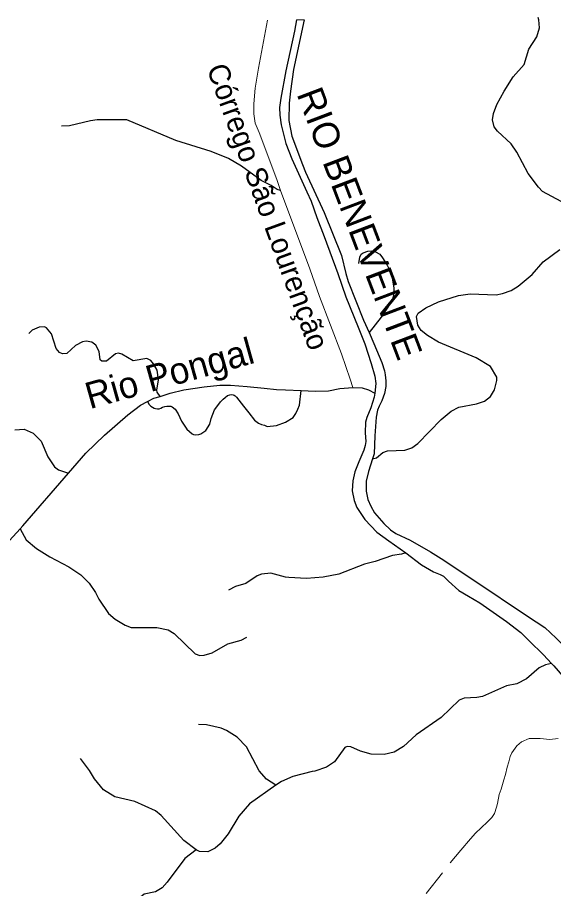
# Model space of a CAD drawing. Extents: x 317.8 to 344.1, y 7676.8 to 7704.8.
# Drawn here: x 325.558 to 327.586, y 7701.313 to 7704.608 of the extents above; entities that cross this region are included whole.
import ezdxf
from ezdxf.enums import TextEntityAlignment as Align

# ---------------------------------------------------------------- set-up
doc = ezdxf.new("R2010")
doc.units = 0
doc.header["$LTSCALE"] = 0.032
doc.linetypes.add('SHORT_DASHED', pattern=[2.7, 1.5, -1.2])
for name, color, linetype, lineweight in [('1', 7, 'Continuous', 13), ('2', 7, 'Continuous', 25), ('21', 7, 'SHORT_DASHED', 13), ('62', 7, 'SHORT_DASHED', 13), ('7', 7, 'Continuous', 25)]:
    doc.layers.add(name, color=color, linetype=linetype, lineweight=lineweight)
doc.layers.add('61', color=7, linetype='Continuous')

msp = doc.modelspace()

# ---------------------------------------------------------------- linework, layer by layer
at = {"layer": '1'}
for points in [[(326.5047, 7704.597), (326.4697, 7704.4161), (326.4572, 7704.3394), (326.453, 7704.2802), (326.453, 7704.2427), (326.458, 7704.2076), (326.4722, 7704.1718), (326.5389, 7703.995), (326.5534, 7703.953)], [(326.5534, 7703.953), (326.6648, 7703.6563), (326.7007, 7703.5521), (326.7841, 7703.3352), (326.8166, 7703.2393), (326.8268, 7703.2079)]]:
    msp.add_lwpolyline(points, dxfattribs=at)
at = {"layer": '2'}
for points in [[(326.6144, 7704.5981), (326.6062, 7704.5552), (326.5733, 7704.4056), (326.5545, 7704.3026), (326.5499, 7704.2663), (326.551, 7704.2382), (326.5557, 7704.2008), (326.5733, 7704.1306), (326.5967, 7704.0732), (326.6529, 7703.948), (326.6693, 7703.9129), (326.6903, 7703.8508), (326.7184, 7703.7794), (326.7699, 7703.639), (326.8003, 7703.5512), (326.8472, 7703.4365), (326.8729, 7703.3733), (326.8963, 7703.2995), (326.9104, 7703.2515), (326.9139, 7703.2234), (326.9097, 7703.1865)], [(326.6424, 7704.5984), (326.6025, 7704.4105), (326.5911, 7704.3285), (326.5865, 7704.2829), (326.5854, 7704.218), (326.5968, 7704.1588), (326.6367, 7704.0518), (326.648, 7704.0222), (326.7186, 7703.8696), (326.7836, 7703.7067), (326.8006, 7703.6395), (326.8097, 7703.6088), (326.8678, 7703.463), (326.8885, 7703.4156)], [(326.8885, 7703.4156), (326.9065, 7703.3742), (326.9361, 7703.3025), (326.9464, 7703.2706), (326.9498, 7703.2558), (326.9521, 7703.233), (326.9521, 7703.2114), (326.9464, 7703.1852), (326.9361, 7703.1578), (326.927, 7703.1373), (326.9202, 7703.1225), (326.9157, 7703.0963), (326.91, 7703.0257), (326.9077, 7702.9574), (326.9014, 7702.938)], [(326.9097, 7703.1865), (326.908, 7703.1719), (326.8952, 7703.131), (326.8799, 7703.0947), (326.8753, 7703.0771), (326.8741, 7703.0362), (326.8764, 7703.0034), (326.8741, 7702.9894), (326.8682, 7702.9706), (326.8495, 7702.9273), (326.8343, 7702.8887), (326.8273, 7702.8548), (326.8249, 7702.8173), (326.8319, 7702.781), (326.8425, 7702.7541), (326.8729, 7702.7096), (326.9174, 7702.6616), (326.963, 7702.6289), (327.0274, 7702.5832)], [(326.9014, 7702.938), (326.886, 7702.8902), (326.8769, 7702.8538), (326.8769, 7702.8162), (326.8838, 7702.7843), (326.8952, 7702.7593), (326.9088, 7702.7342), (326.9441, 7702.6943), (326.9692, 7702.6704), (326.9897, 7702.6556), (327.0443, 7702.6306), (327.1206, 7702.5862), (327.1605, 7702.5611), (327.2846, 7702.4791), (327.4873, 7702.3436), (327.5534, 7702.3003), (327.5955, 7702.2605), (327.6308, 7702.2252)], [(327.0274, 7702.5832), (327.0871, 7702.5376), (327.1316, 7702.5106), (327.1573, 7702.5013), (327.1702, 7702.4942), (327.1889, 7702.4755), (327.2276, 7702.4404), (327.2638, 7702.4193), (327.3072, 7702.3936), (327.4078, 7702.3234), (327.4617, 7702.2812), (327.4944, 7702.2496), (327.5483, 7702.1969), (327.5785, 7702.1649)], [(327.5785, 7702.1649), (327.5869, 7702.156), (327.6279, 7702.1092)]]:
    msp.add_lwpolyline(points, dxfattribs=at)
at = {"layer": '21'}
msp.add_lwpolyline([(327.1038, 7701.2943), (327.1947, 7701.4103), (327.2352, 7701.4592), (327.2715, 7701.5011), (327.2911, 7701.5235), (327.312, 7701.543), (327.3358, 7701.5654), (327.3525, 7701.5821), (327.3623, 7701.5975), (327.3707, 7701.6213), (327.3735, 7701.6352), (327.3805, 7701.6688), (327.3875, 7701.6897), (327.3986, 7701.7247), (327.4042, 7701.7442), (327.4112, 7701.7722), (327.4168, 7701.7931), (327.4224, 7701.8127), (327.428, 7701.8267), (327.4475, 7701.8532), (327.4643, 7701.8686), (327.4937, 7701.8811), (327.5356, 7701.8811), (327.5719, 7701.877), (327.604, 7701.8811)], dxfattribs=at)
at = {"layer": '62'}
msp.add_line((326.6144, 7704.5981), (326.6424, 7704.5984), dxfattribs=at)
at = {"layer": '7'}
for points in [[(327.6142, 7703.9111), (327.5447, 7703.9491), (327.5287, 7703.9651), (327.4899, 7704.0174), (327.4468, 7704.0985), (327.4256, 7704.1299), (327.3737, 7704.1771), (327.3617, 7704.1938), (327.3557, 7704.2199), (327.3594, 7704.2438), (327.3721, 7704.2778), (327.3994, 7704.3292), (327.4331, 7704.3826), (327.4746, 7704.4292), (327.4931, 7704.4874), (327.5223, 7704.5345), (327.5325, 7704.5682), (327.53, 7704.5986), (327.5274, 7704.6075)], [(326.5534, 7703.953), (326.5404, 7703.9574), (326.5184, 7703.9724), (326.4804, 7703.9904), (326.4059, 7704.0446), (326.357, 7704.0735), (326.291, 7704.1007), (326.1577, 7704.1423), (325.9728, 7704.2198), (325.8603, 7704.2204), (325.8342, 7704.2171), (325.7552, 7704.1977), (325.7249, 7704.1961)], [(326.8492, 7703.6769), (326.8533, 7703.7007), (326.859, 7703.7121), (326.8656, 7703.7179), (326.8836, 7703.7236), (326.8975, 7703.7244), (326.9122, 7703.7211), (326.9286, 7703.7129), (326.9393, 7703.699), (326.9565, 7703.6712), (326.9704, 7703.6425), (326.9769, 7703.6155), (326.9819, 7703.5835), (326.981, 7703.559), (326.9769, 7703.5418), (326.9598, 7703.5123), (326.9335, 7703.4738), (326.8885, 7703.4156)], [(326.9014, 7702.938), (326.917, 7702.9424), (326.9408, 7702.962), (326.9582, 7702.9687), (327.0237, 7702.9709), (327.0495, 7702.9802), (327.0733, 7702.9961), (327.1614, 7703.0874), (327.1987, 7703.1185), (327.2284, 7703.1337), (327.294, 7703.1463), (327.3253, 7703.1564), (327.3472, 7703.1738), (327.3631, 7703.1991), (327.3711, 7703.234), (327.3711, 7703.2467), (327.3475, 7703.2872), (327.2937, 7703.3207), (327.1509, 7703.3798), (327.1095, 7703.4047), (327.0859, 7703.4234), (327.073, 7703.4443), (327.068, 7703.4771), (327.0741, 7703.4891), (327.103, 7703.5089), (327.1513, 7703.5322), (327.2259, 7703.5564), (327.2705, 7703.5628), (327.3692, 7703.5588), (327.3926, 7703.563), (327.426, 7703.5751), (327.4526, 7703.5919), (327.5045, 7703.6359), (327.5466, 7703.6835), (327.6102, 7703.7295)], [(326.0986, 7703.1746), (326.0874, 7703.1907), (326.0859, 7703.1985), (326.0923, 7703.2369), (326.0865, 7703.2737), (326.0734, 7703.298), (326.0634, 7703.3096), (326.0477, 7703.318), (325.9959, 7703.3086), (325.9529, 7703.3336), (325.9403, 7703.3379), (325.929, 7703.3359), (325.8949, 7703.308), (325.8771, 7703.3072), (325.8717, 7703.3126), (325.8681, 7703.3438), (325.8552, 7703.3688), (325.8397, 7703.3793), (325.8184, 7703.3827), (325.8042, 7703.381), (325.7786, 7703.3671), (325.7455, 7703.3364), (325.7284, 7703.3353), (325.7176, 7703.3403), (325.7047, 7703.3558), (325.6874, 7703.4108), (325.669, 7703.4336), (325.6603, 7703.4373), (325.6408, 7703.4364), (325.6142, 7703.425), (325.601, 7703.4129)], [(326.0502, 7703.1547), (326.0563, 7703.1441), (326.0626, 7703.1377), (326.069, 7703.134), (326.075, 7703.1306), (326.0806, 7703.1284), (326.088, 7703.1273), (326.0948, 7703.128), (326.1004, 7703.1306), (326.1075, 7703.1336), (326.1164, 7703.1359), (326.1239, 7703.137), (326.1329, 7703.1377), (326.1388, 7703.1374), (326.1441, 7703.1355), (326.1555, 7703.1258), (326.1664, 7703.1082), (326.1795, 7703.0813), (326.1996, 7703.0503), (326.2189, 7703.0331), (326.2245, 7703.0309), (326.2316, 7703.0294), (326.2443, 7703.0305), (326.2518, 7703.0331), (326.2705, 7703.0451), (326.2857, 7703.0694), (326.2917, 7703.0914), (326.3032, 7703.1234), (326.3159, 7703.1402), (326.3263, 7703.154), (326.3364, 7703.1641), (326.3447, 7703.1709), (326.3529, 7703.1776), (326.3615, 7703.1806), (326.3686, 7703.1817), (326.3745, 7703.1806), (326.3779, 7703.1787), (326.3816, 7703.1761), (326.3865, 7703.1716), (326.4139, 7703.1379), (326.4333, 7703.1125), (326.4547, 7703.0846), (326.4697, 7703.0738), (326.4816, 7703.0686), (326.4925, 7703.0652), (326.5029, 7703.0602), (326.538, 7703.0643), (326.5727, 7703.077), (326.6011, 7703.095), (326.6112, 7703.1092), (326.6191, 7703.1256), (326.6247, 7703.1417), (326.632, 7703.1964)], [(326.0986, 7703.1746), (326.1363, 7703.1873), (326.1875, 7703.1998), (326.2647, 7703.2108), (326.3235, 7703.2171), (326.3648, 7703.2167), (326.427, 7703.2123), (326.4921, 7703.205), (326.5377, 7703.2006), (326.5722, 7703.1996), (326.632, 7703.1964)], [(326.632, 7703.1964), (326.685, 7703.1938), (326.7355, 7703.1958), (326.7782, 7703.204), (326.8268, 7703.2079)], [(326.8268, 7703.2079), (326.8628, 7703.2069), (326.8866, 7703.1996), (326.9097, 7703.1865)], [(326.0502, 7703.1547), (326.0748, 7703.1676), (326.0986, 7703.1746)], [(325.751, 7702.8836), (325.8172, 7702.9599), (325.888, 7703.0276), (325.9764, 7703.1044), (326.0241, 7703.141), (326.0502, 7703.1547)], [(325.5489, 7703.0475), (325.5838, 7703.0501), (325.6183, 7703.0352), (325.6485, 7703.0055), (325.6733, 7702.9459), (325.699, 7702.9081), (325.7134, 7702.8962), (325.751, 7702.8836)], [(325.5684, 7702.6735), (325.5786, 7702.6846), (325.751, 7702.8836)], [(325.2948, 7702.3678), (325.4161, 7702.5084), (325.5684, 7702.6735)], [(325.5684, 7702.6735), (325.5914, 7702.6326), (325.6302, 7702.5994), (325.6811, 7702.5672), (325.7533, 7702.5303), (325.7987, 7702.4994), (325.8299, 7702.4682), (325.854, 7702.4329), (325.8662, 7702.4073), (325.9033, 7702.354), (325.9281, 7702.332), (325.9655, 7702.3091), (325.9881, 7702.3004), (326.086, 7702.3012), (326.1285, 7702.292), (326.1513, 7702.2781), (326.2302, 7702.2007), (326.2483, 7702.1952), (326.2645, 7702.1961), (326.2954, 7702.2053), (326.3548, 7702.2383), (326.4046, 7702.2529), (326.4258, 7702.2645)], [(327.0274, 7702.5832), (327.0114, 7702.5777), (326.9775, 7702.5733), (326.9114, 7702.5503), (326.8706, 7702.5404), (326.7735, 7702.5021), (326.7153, 7702.4914), (326.6521, 7702.4854), (326.5853, 7702.4902), (326.5729, 7702.4911), (326.5166, 7702.5066), (326.4813, 7702.5023), (326.4646, 7702.4965), (326.4222, 7702.4676), (326.3833, 7702.4551), (326.3573, 7702.4414)], [(327.5785, 7702.1649), (327.5557, 7702.1589), (327.5311, 7702.148), (327.4837, 7702.107), (327.4472, 7702.0877), (327.4079, 7702.0794), (327.3176, 7702.0402), (327.2956, 7702.0355), (327.248, 7702.0337), (327.2296, 7702.0254), (327.1611, 7701.9608), (327.0665, 7701.8948), (327.0188, 7701.8501), (326.9837, 7701.8291), (326.9454, 7701.8206), (326.8957, 7701.822), (326.8563, 7701.8329), (326.819, 7701.8496), (326.8061, 7701.8503), (326.7966, 7701.8471), (326.7571, 7701.7931), (326.7275, 7701.7719), (326.6835, 7701.7569), (326.6726, 7701.7566), (326.5996, 7701.7372), (326.5568, 7701.7187), (326.5358, 7701.7038)], [(326.5358, 7701.7038), (326.501, 7701.727), (326.4729, 7701.7582), (326.425, 7701.8493), (326.39, 7701.8863), (326.3489, 7701.9112), (326.3284, 7701.9197), (326.2741, 7701.9327), (326.2432, 7701.9336)], [(326.2346, 7701.4595), (326.1878, 7701.4958), (326.1019, 7701.5897), (326.0804, 7701.607), (326.0026, 7701.6425), (325.9272, 7701.6597), (325.8838, 7701.6866), (325.8494, 7701.7288), (325.8315, 7701.7599), (325.7966, 7701.8057)], [(326.5358, 7701.7038), (326.4361, 7701.6334), (326.396, 7701.5873), (326.3549, 7701.5198), (326.3246, 7701.4828), (326.3057, 7701.4666), (326.2784, 7701.4527), (326.2473, 7701.4541), (326.2346, 7701.4595)], [(326.2346, 7701.4595), (326.1921, 7701.4276), (326.1253, 7701.338), (326.1059, 7701.3162), (326.0809, 7701.3008), (326.0384, 7701.2925), (326.0239, 7701.2805), (326.0126, 7701.2449)]]:
    msp.add_lwpolyline(points, dxfattribs=at)

# ---------------------------------------------------------------- texts
at = {"layer": '61'}
for s, height, rotation, p in [('Córrego São Lourenção', 0.08, 289.983, (326.4685, 7703.8786)), ('RIO BENEVENTE', 0.1, 290.807, (326.8061, 7703.8113)), ('Rio Pongal', 0.1, 15.667, (326.1467, 7703.2142))]:
    msp.add_text(s, height=height, rotation=rotation, dxfattribs=at).set_placement(p, align=Align.CENTER)

doc.saveas('drawing.dxf')
